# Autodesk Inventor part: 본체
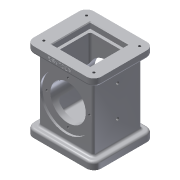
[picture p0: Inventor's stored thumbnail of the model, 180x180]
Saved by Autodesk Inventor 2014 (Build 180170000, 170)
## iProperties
Created: 2017-08
Part Number: 본체
Material: 알루미늄 6061
Document SubType Name: Modeling
Designer: user
Density: 2.71 g/cm^3
Appearance: 알루미늄 - 평지
Mass: 872.287 g
Surface Area: 641.287 cm^2
Volume: 321.877 cm^3
Author: user
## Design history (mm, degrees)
sketch "스케치1"
  geometry: L1 (46, 41)-(-46, 41); L2 (-46, 41)-(-46, -41); L3 (-46, -41)-(46, -41); L4 (46, -41)-(46, 41); L5 (46, 41)-(-46, -41); L6 (-46, 41)-(46, -41); 1 further point
  constraints: 12 end point, 2 midpoint, 2 parallel, 1 horizontal, 1 perpendicular
  dimensions: "d0" = 92 distance of L2.end L3.end; "d1" = 82 distance of L1.end L2.end
extrude "돌출1" new body sketch "스케치1" distance "d2" = 10; taper "d3" = 0 deg
node "작업 평면1"
sketch "스케치2"
  geometry: L1 (37, -33)-(-37, -33); L2 (-37, -33)-(-37, 33); L3 (-37, 33)-(37, 33); L4 (37, 33)-(37, -33); L5 (37, -33)-(-37, 33); L6 (-37, -33)-(37, 33); 1 further point
  constraints: 12 end point, 2 midpoint, 2 parallel, 1 horizontal, 1 perpendicular
  dimensions: "d5" = 74 distance of L2.end L3.end; "d6" = 66 distance of L1.end L2.end
extrude "돌출2" join sketch "스케치2" stored distance "d7" = 88; taper "d8" = 0 deg
sketch "스케치3"
  geometry: L1 (-46, 41)-(46, 41); L2 (46, 41)-(46, -41); L3 (46, -41)-(-46, -41); L4 (-46, -41)-(-46, 41); L5 (-46, 41)-(46, -41); L6 (46, 41)-(-46, -41); 1 further point
  constraints: 12 end point, 2 midpoint, 2 parallel, 1 horizontal, 1 perpendicular
  dimensions: "d9" = 92 distance of L2.end L3.end; "d10" = 82 distance of L1.end L2.end
extrude "돌출3" join sketch "스케치3" distance "d11" = 10; taper "d12" = 0 deg
sketch "스케치4"
  geometry: C1 r 35 at (37, 44); 1 further point
  constraints: 1 centre point
  dimensions: "d13" = 70 diameter of C1
extrude "돌출4" cut sketch "스케치4" distance "d14" = 3; taper "d15" = 0 deg
sketch "스케치5"
  geometry: C1 r 35 at (0, 0) reference; 2 further points
  constraints: 1 coincident
hole "구멍1" sketch "스케치5" at (0, 0) diameter "d16" = 48; stored, may be unused: countersink angle "d20" = 90 deg, drill point angle "d22" = 0 deg; dims "d17" = 6, "d18" = 4, "d19" = 2, "d21" = 8
sketch "스케치6" dims "d23" = 58
  geometry: C1 r 35 at (0, 0) reference; 3 further points
  constraints: 1 coincident, 1 vertical alignment, 2 other
hole "구멍2" sketch "스케치6" at (0, 29) diameter "d24" = 3.242; stored, may be unused: countersink angle "d28" = 90 deg, drill point angle "d30" = 118 deg; dims "d25" = 4, "d26" = 4, "d27" = 2, "d29" = 6
sketch "스케치7"
  geometry: L1 (46, 41)-(-46, 41) reference; L2 (46, -41)-(46, 41) reference; L3 (0, 0)-(0, 41); L4 (0, 0)-(46, 0); 4 further points
  constraints: 4 end point, 2 midpoint, 2 symmetric about line
  dimensions: "d34" = 72 distance of point (-36, 31) point (36, 31); "d35" = 62 distance of point (36, 31) point (36, -31)
hole "구멍3" sketch "스케치7" at (-36, 31), (36, 31), (-35.443, -27.495), (36, -31) diameter "d36" = 3.242; stored, may be unused: countersink angle "d40" = 90 deg, drill point angle "d42" = 118 deg; dims "d37" = 4, "d38" = 4, "d39" = 2, "d41" = 6
sketch "스케치8"
  geometry: L1 (-46, 41)-(46, 41) reference; L2 (46, 41)-(46, -41) reference; L3 (0, 0)-(0, 41); L4 (0, 0)-(46, 0); 4 further points
  constraints: 4 end point, 2 midpoint, 2 symmetric about line
  dimensions: "d43" = 72 distance of point (36, 31) point (-36, 31); "d44" = 62 distance of point (36, -31) point (36, 31); "d45" = 62 distance of point (-36, -31) point (-36, 31); "d46" = 72 distance of point (36, -31) point (-36, -31)
hole "구멍4" sketch "스케치8" at (-36, 31), (36, 31), (36, -31), (-36, -31) diameter "d47" = 3.242; stored, may be unused: countersink angle "d51" = 90 deg, drill point angle "d53" = 118 deg; dims "d48" = 4, "d49" = 4, "d50" = 2, "d52" = 6
sketch "스케치9"
  geometry: L1 (-26, 26)-(26, 26); L2 (26, 26)-(26, -26); L3 (26, -26)-(-26, -26); L4 (-26, -26)-(-26, 26); L5 (-26, 26)-(26, -26); L6 (26, 26)-(-26, -26); 1 further point
  constraints: 12 end point, 2 midpoint, 2 parallel, 1 horizontal, 1 perpendicular
  dimensions: "d54" = 52 distance of L2.end L3.end; "d55" = 52 distance of L1.end L2.end
extrude "돌출5" cut sketch "스케치9" distance "d56" = 8; taper "d57" = 0 deg
sketch "스케치10"
  geometry: L1 (-22, 22)-(22, 22); L2 (22, 22)-(22, -22); L3 (22, -22)-(-22, -22); L4 (-22, -22)-(-22, 22); L5 (-22, 22)-(22, -22); L6 (22, 22)-(-22, -22); 1 further point
  constraints: 12 end point, 2 midpoint, 2 parallel, 1 horizontal, 1 perpendicular
  dimensions: "d58" = 44 distance of L2.end L3.end; "d59" = 44 distance of L1.end L2.end
extrude "돌출6" cut sketch "스케치10" distance "d60" = 74; taper "d61" = 0 deg
sketch "스케치11"
  geometry: L1 (-24, 24)-(24, 24); L2 (24, 24)-(24, -24); L3 (24, -24)-(-24, -24); L4 (-24, -24)-(-24, 24); L5 (-24, 24)-(24, -24); L6 (24, 24)-(-24, -24); 1 further point
  constraints: 12 end point, 2 midpoint, 2 parallel, 1 horizontal, 1 perpendicular
  dimensions: "d62" = 48 distance of L2.end L3.end; "d63" = 48 distance of L1.end L2.end
extrude "돌출7" cut sketch "스케치11" distance "d64" = 16; taper "d65" = 0 deg
sketch "스케치12"
  geometry: L1 (-8, -10)-(74, -10) reference; 2 further points
  dimensions: "d66" = 38 distance from line of L1 point (33, 28)
hole "구멍5" sketch "스케치12" at (33, 28) diameter "d67" = 4.134; stored, may be unused: countersink angle "d71" = 90 deg, drill point angle "d73" = 0 deg; dims "d68" = 25, "d69" = 4, "d70" = 2, "d72" = 6
sketch "스케치13"
  geometry: C1 r 2.067 at (33, 28) reference; 2 further points
  dimensions: "d74" = 42 distance of C1.centre point (33, 70)
hole "구멍6" sketch "스케치13" at (33, 70) diameter "d75" = 4.134; stored, may be unused: countersink angle "d79" = 90 deg, drill point angle "d81" = 0 deg; dims "d76" = 25, "d77" = 4, "d78" = 2, "d80" = 6
fillet "모깎기1" dims "d82" = 3
fillet "모깎기2" dims "d83" = 3
fillet "모깎기3" dims "d84" = 3
fillet "모깎기4" dims "d85" = 3
fillet "모깎기5" dims "d86" = 10
chamfer "모따기1" distance "d87" = 1; stored, may be unused: second distance "d88" = 2, angle "d89" = 45 deg
fillet "모깎기6" dims "d90" = 3
sketch "스케치14"
  geometry: L1 (0, 7)-(72, 7) reference; L2 (19.408, 5.402)-(52.592, 5.402); L3 (52.592, 5.402)-(52.592, 0.598); L4 (52.592, 0.598)-(19.408, 0.598); L5 (19.408, 0.598)-(19.408, 5.402); L6 (19.408, 0.598)-(52.592, 5.402); L7 (52.592, 0.598)-(19.408, 5.402); L8 (-10, 7)-(-10, 0) reference; 2 further points
  constraints: 4 end point, 1 midpoint, 2 other
  dimensions: "d91" = 46 distance from line of point (36, 3) L8; "d92" = 4 distance from line of L1 point (36, 3)
feature "엠보싱1" sketch "스케치14" dims "d0" = 92, "d1" = 82, "d9" = 92, "d10" = 82, "d93" = 0.5, "d94" = 0
node "솔리드1"
mirror "대칭1"
pattern_circular "원형 패턴1" dims angle "d32" = 360 deg
mirror "대칭2"
other parameters: "d4" = 54
